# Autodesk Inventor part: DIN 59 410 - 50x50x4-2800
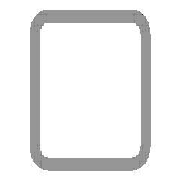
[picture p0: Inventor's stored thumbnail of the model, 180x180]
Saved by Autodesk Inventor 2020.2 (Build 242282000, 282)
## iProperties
Manager: www.cadconsulting.pl
Company: Fabian Stasiak CAD Consulting
IsCustomPart: 1
_CCFamilyMember: 40
_CCFamilyDisplayName: DIN 59410 (Kwadrat) - Rurki stalowe o przekroju kwadratowym formowane na gorąco
_FrameMemberDoc: Frame Member File
_Version: 15.0.0
_GetPNFromCC: 1
Created: 2015-01
Part Number: DIN 59 410 - 50x50x4-2800
Material: Stal, miękka
Description: Rurki stalowe o przekroju kwadratowym formowane na gorąco
Document SubType Name: Modellieren
Standard: DIN
Designer: F.Stasiak
Standards Organization: DIN
Language: pl-PL
Size Designation: 50x50x4
Categories: <MemberInstance><Categories><Category DisplayName="Kształtowniki konstrukcyjne" InternalName="089c4875-fa83-4c05-b084-43b9cc11f5ed" Mnemonic="GRDR"><CategoryPar
Stock Number: 50x50x4
Density: 7.85 g/cm^3
Appearance: Częściowo polerowana
Mass: 15189.8 g
Surface Area: 9691.81 cm^2
Volume: 1935.01 cm^3
Catalog Web Link: www.expertbooks.pl
G_W: 50,000 mm
G_H: 50,000 mm
+D23F4B60-F1AB-4C70-B588-4AD65F3BC300+CUTDETAIL1: Połączenie narożnikowe 45,00 deg
G_L: 2800,000 mm
+B3489DAB-EAB6-41E3-B670-C03B2D428CA9+CUTDETAIL4: Wytnij
Author: F.Stasiak
Subject: Zbiór ćwiczeń. Autodesk Inventor 2020. Kurs Professional
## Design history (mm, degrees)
node "Płaszczyzna początkowa"
node "Płaszczyzna końcowa"
sketch "Szkic1"
  geometry: L1 (-17, 25)-(17, 25); L2 (25, 17)-(25, -17); L3 (17, -25)-(-17, -25); L4 (-25, -17)-(-25, 17); L5 (-37.32, 0)-(37.32, 0) reference; L6 (0, -37.32)-(0, 37.32) reference; L7 (-17, 21)-(17, 21); L8 (21, 17)-(21, -17); L9 (17, -21)-(-17, -21); L10 (-21, -17)-(-21, 17); A1 r 8 centre (-17, 17) between (-17, 25) and (-25, 17); A2 r 8 centre (17, 17) between (25, 17) and (17, 25); A3 r 8 centre (17, -17) between (17, -25) and (25, -17); A4 r 8 centre (-17, -17) between (-25, -17) and (-17, -25); A5 r 4 centre (-17, 17) between (-17, 21) and (-21, 17); A6 r 4 centre (17, 17) between (21, 17) and (17, 21); A7 r 4 centre (17, -17) between (17, -21) and (21, -17); A8 r 4 centre (-17, -17) between (-21, -17) and (-17, -21); 3 further points
  constraints: 16 end point, 16 point on circle, 8 centre point, 8 tangent, 6 point on line, 4 parallel, 3 equal radius, 3 perpendicular, 1 horizontal, 7 other
  dimensions: "b" = 50 distance of point (-25, 25) point (25, 25); "msp_r" = 8 radius of A1 (= 2 x ParT); "d8" = 25 distance between parallel lines of L4 L6 (= d9); "d9" = 25 distance between parallel lines of L3 L5 (= 0.5 x b); "d10" = 4 distance between parallel lines of L3 L9 (= ParT)
extrude "Bryła" new body sketch "Szkic1" taper "d4" = 0 deg; stored distance "NLG" = 10
node "Driven Length"
  sketch "Sketch2"
    geometry: L1 (0, 0)-(10, 0) reference
    constraints: 2 end point, 1 horizontal
  workplane "Work Plane3"
  sketch "Sketch3"
    geometry: L1 (-2, -25)-(12, -25) reference; L2 (-2, 2775)-(12, 2775) reference
    dimensions: "d14" = 2800 distance between parallel lines of L1 L2 (derived)
node "Płaszczyzna konstrukcyjna4"
feature "Podział1"
node "Płaszczyzna konstrukcyjna7"
feature "Podział4"
body "Solid1"
other parameters: "ParT" = 4, "G_OFFSET_START" = 25 [user parameter; used in 1 equation term], "G_OFFSET_END" = 25 [user parameter; used in 1 equation term], "d11" = -25 (= -G_OFFSET_START), "d12" = 2775 (= G_OFFSET_END + B_L), "G_L" = 2800 (= d14) [user parameter], "d13" = 90 deg
